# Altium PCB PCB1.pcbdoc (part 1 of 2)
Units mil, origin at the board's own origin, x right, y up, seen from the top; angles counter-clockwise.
Board outline 3120 x 2755.91 mil, 2 copper layers (Top Layer, Bottom Layer), stack 62.205 mil thick; 41 components, 124 nets, 614 pads, 395 vias.
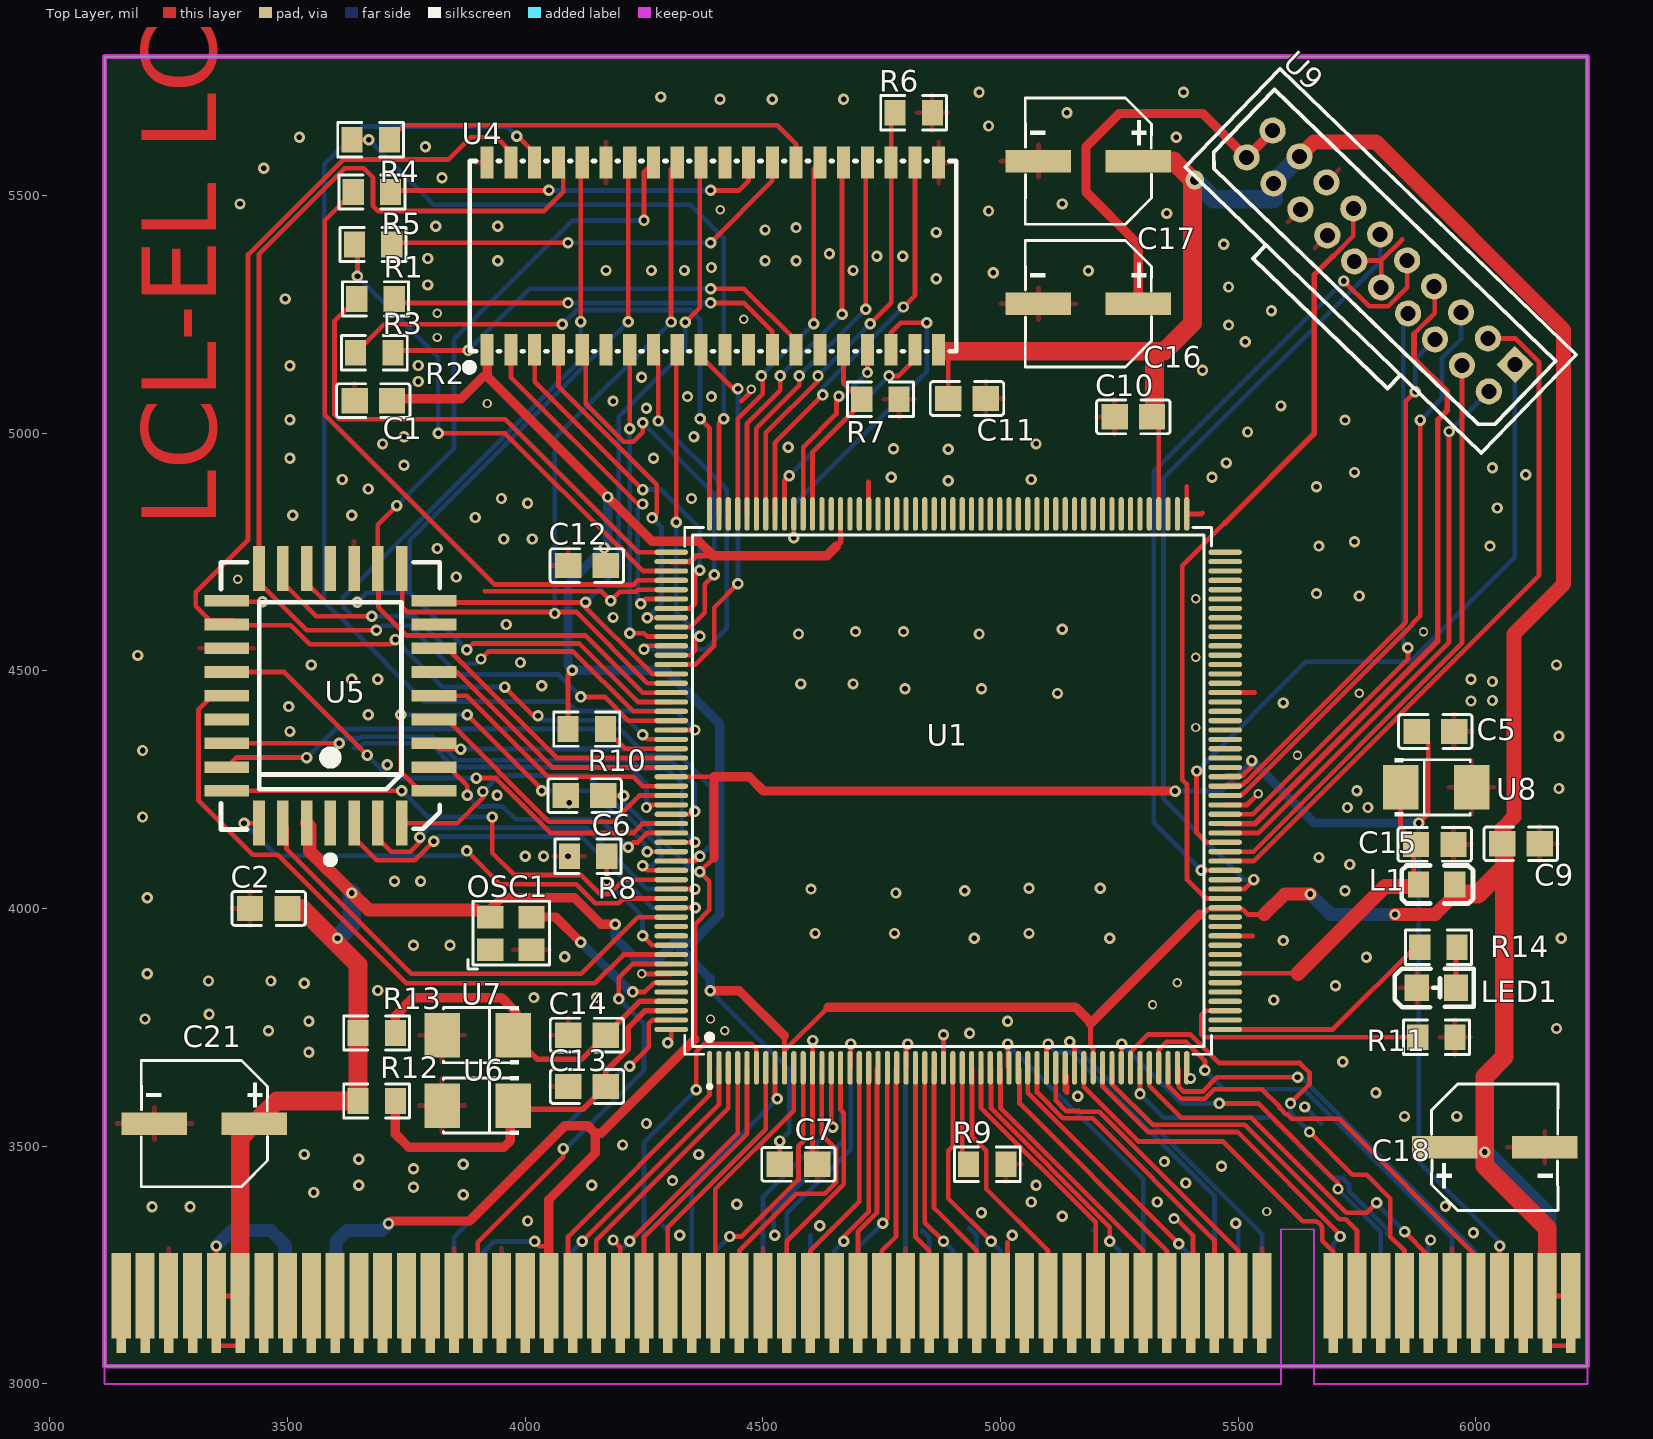
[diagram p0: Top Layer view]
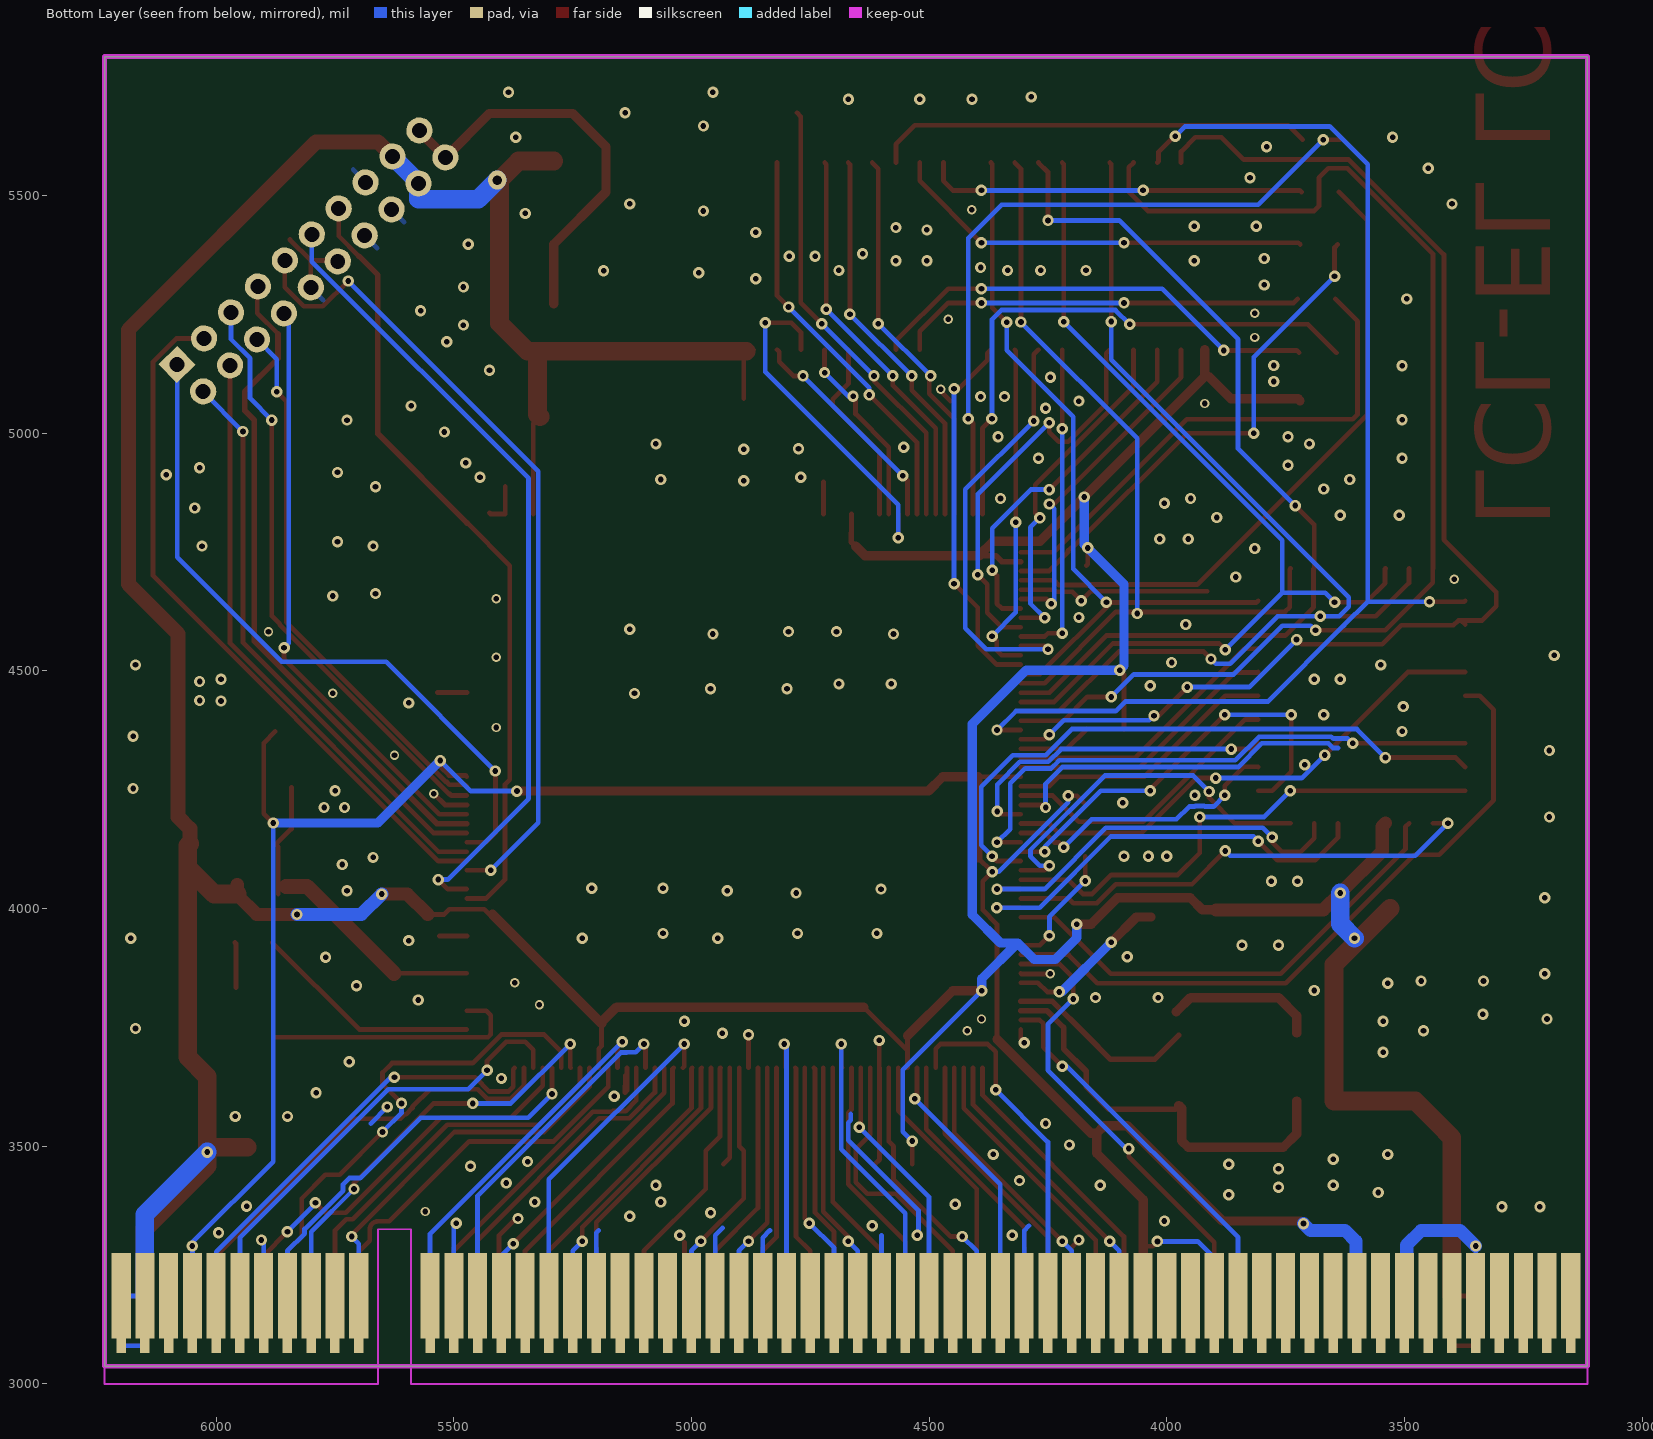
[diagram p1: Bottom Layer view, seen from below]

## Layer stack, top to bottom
Top Solder Mask Layer: solder mask 0.394, Dk 3.3
Top Layer: signal copper 1.378
Dielectric1: surface 59.449, FR4, Dk 4.5
Bottom Layer: signal copper 1.378
Bottom Solder Mask Layer: solder mask 0.394, Dk 3.3

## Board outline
3115,3036.77 3115,5792.68 6235,5792.68 6235,3036.77

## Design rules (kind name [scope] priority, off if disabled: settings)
BoardOutlineClearance copperThickness1oz [All] p0: genericclearance=10 ignorepadtopadclearanceinfootprint=FALSE except(0: Arc-SplitContinuation Track-SplitContinuation SMDPad-SplitContinuation THPad-SplitContinuation Via-SplitContinuation Fill-SplitContinuation Poly-SplitContinuation Region-SplitContinuation Text-SplitContinuation)
BoardOutlineClearance copperThickness2oz [All] p0: genericclearance=10 ignorepadtopadclearanceinfootprint=FALSE except(0: Arc-SplitContinuation Track-SplitContinuation SMDPad-SplitContinuation THPad-SplitContinuation Via-SplitContinuation Fill-SplitContinuation Poly-SplitContinuation Region-SplitContinuation Text-SplitContinuation)
BoardOutlineClearance otherClearance [All] p0: genericclearance=10 ignorepadtopadclearanceinfootprint=FALSE except(0: Arc-SplitContinuation Track-SplitContinuation SMDPad-SplitContinuation THPad-SplitContinuation Via-SplitContinuation Fill-SplitContinuation Poly-SplitContinuation Region-SplitContinuation Text-SplitContinuation)
Clearance copperThickness1oz [All] p1: gap=7 ignorepadtopadclearanceinfootprint=FALSE
Clearance copperThickness2oz [All] p1: gap=7 ignorepadtopadclearanceinfootprint=FALSE
Clearance otherClearance [All] p1: gap=7 ignorepadtopadclearanceinfootprint=FALSE
DiffPairsRouting differentialPair [All] p1: maxuncoupledlength=10 minlimit=6 maxlimit=Infinity mostfreqgap=6 toplayer_minwidth=5 toplayer_prefwidth=10 toplayer_maxwidth=100 bottomlayer_minwidth=5 bottomlayer_prefwidth=10 bottomlayer_maxwidth=100
PasteMaskExpansion pasteMaskExpansion [All] p1: expansion=0
PlaneConnect innerPlane [All] p1: planeconnectstyle=Relief reliefexpansion=20 reliefentries=4 reliefconductorwidth=10 reliefairgap=10
PolygonConnect copperRegion [All] p1: connectstyle=Relief reliefentries=4 reliefconductorwidth=10 polygonreliefangle="90 Angle" airgapwidth=10
RoutingVias viaSize [All] p1: viastyle="Through Hole" holewidth=12.0078 minholewidth=11.811 maxholewidth=248.0314 width=12.0078 minwidth=11.811 maxwidth=248.0314
SolderMaskExpansion solderMaskExpansion [All] p1: useseparateexpansions=TRUE expansion=2 expansionbottom=2
Width copperThickness1oz [All] p1: maxlimit=100 minlimit=5 preferedwidth=10
Width copperThickness2oz [All] p1: maxlimit=100 minlimit=8 preferedwidth=10

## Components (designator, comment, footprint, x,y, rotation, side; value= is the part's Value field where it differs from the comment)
C1 "" C0805 3680.43,5068.67 r0 top
C2 "" C0805 3460.43,4000.26 r0 top
C5 "" C0805 5915,4372.68 r180 top
C6 "" C0805 4125,4237.68 r0 top
C7 "" C0805 4574.89,3461.83 r180 top
C9 "" C0805 6094.89,4136.34 r180 top
C10 "" C0805 5279.55,5034.5 r0 top
C11 "" C0805 4929.55,5073.17 r180 top
C12 "" C0805 4129.88,4721.6 r0 top
C13 "" C0805 4130.18,3625.57 r0 top
C14 "" C0805 4130.18,3733.67 r0 top
C15 "" C0805 5913.72,4135.01 r180 top
C16 "" CAP-SMD_BD6.3-L6.6-W6.6-LS7.3-FD 5185,5272.68 r180 top
C17 "" CAP-SMD_BD6.3-L6.6-W6.6-LS7.3-FD 5185,5572.68 r180 top
C18 "" CAP-SMD_BD6.3-L6.6-W6.6-LS7.3-FD 6040,3497.68 r0 top
C21 "" CAP-SMD_BD6.3-L6.6-W6.6-LS7.3-FD 3325,3547.68 r180 top
L1 "" L0805 5917.8,4050.44 r180 top
LED1 "" LED0805-FD 5917.16,3833.52 r180 top
OSC1 "" OSC-SMD_4P-L3.2-W2.5-BL 3970,3947.68 r0 top
R1 "" R0805 3685,5282.68 r0 top
R2 "" R0805 3682.5,5169.31 r0 top
R3 "" R0805 3680,5397.21 r180 top
R4 "" R0805 3675,5617.68 r180 top
R5 "" R0805 3677.5,5507.68 r180 top
R6 "" R0805 4817.34,5674.31 r0 top
R7 "" R0805 4747.34,5071.42 r0 top
R8 "" R0805 4132.34,4110.11 r180 top
R9 "" R0805 4972.34,3462.21 r0 top
R10 "" R0805 4129.55,4377.63 r180 top
R11 "" R0805 5917.22,3729.23 r180 top
R12 "" R0805 3687.51,3595.11 r180 top
R13 "" R0805 3687.51,3738.2 r180 top
R14 "" R0805 5921.4,3918.52 r0 top
U1 "" PQFP-208_L28.0-W28.0-P0.50-LS30.6-BL 4890,4247.68 r0 top
U4 "" SOJ-40_L26.0-W10.2-P1.27-LS11.2-BL 4395,5372.68 r0 top
U5 "" PLCC-32_L14.0-W11.4-P1.27-LS15.0-T 3590,4447.68 r180 top
U6 "" CAP-SMD_L3.5-W2.8-R-RD 3899.88,3585.57 r0 top
U7 "" CAP-SMD_L3.5-W2.8-R-RD 3899.88,3733.67 r0 top
U8 "" CAP-SMD_L3.5-W2.8-R-RD 5916.59,4255.01 r180 top
U9 "" 20PIN-2.0MM_2_10 5800,5362.68 r316 top
? "" BUS_PCI-KiCAD 4675,3132.68 r0 top

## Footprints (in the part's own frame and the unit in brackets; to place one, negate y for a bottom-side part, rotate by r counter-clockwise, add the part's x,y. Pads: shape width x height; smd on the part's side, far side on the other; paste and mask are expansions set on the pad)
20PIN-2.0MM_2_10 [mm]
  rect 1.4x1.4 hole 0.8: 1(9,1)
  round 1.4 hole 0.8: 2(9,-1) 3(7,1) 4(7,-1) 5(5,1) 6(5,-1) 7(3,1) 8(3,-1) 9(1,1) 10(1,-1) 11(-1,1) 12(-1,-1) 13(-3,1) 14(-3,-1) 15(-5,1) 16(-5,-1) 17(-7,1) 18(-7,-1) 19(-9,1) 20(-9,-1)
  silkscreen extent -11,-4.65 11,3.65
BUS_PCI-KiCAD [mm]
  rect 0.51x0.76 smd far side: A1(-38.73,-1.33) A2(-37.46,-1.33) A3(-36.2,-1.33) A4(-34.92,-1.33) A5(-33.65,-1.33) A6(-32.38,-1.33) A7(-31.11,-1.33) A8(-29.84,-1.33) A9(-28.57,-1.33) A10(-27.3,-1.33) A11(-26.03,-1.33) A12(-24.77,-1.33) A13(-23.49,-1.33) A14(-22.22,-1.33) A15(-20.95,-1.33) A16(-19.68,-1.33) A17(-18.41,-1.33) A18(-17.14,-1.33) A19(-15.88,-1.33) A20(-14.6,-1.33) A21(-13.34,-1.33) A22(-12.06,-1.33) A23(-10.79,-1.33) A24(-9.52,-1.33) A25(-8.25,-1.33) A26(-6.98,-1.33) A27(-5.71,-1.33) A28(-4.44,-1.33) A29(-3.17,-1.33) A30(-1.9,-1.33) A31(-0.63,-1.33) A32(0.64,-1.33) A33(1.91,-1.33) A34(3.18,-1.33) A35(4.45,-1.33) A36(5.72,-1.33) A37(6.99,-1.33) A38(8.26,-1.33) A39(9.53,-1.33) A40(10.8,-1.33) A41(12.07,-1.33) A42(13.34,-1.33) A43(14.61,-1.33) A44(15.88,-1.33) A45(17.15,-1.33) A46(18.42,-1.33) A47(19.69,-1.33) A48(20.96,-1.33) A49(22.23,-1.33) A52(26.04,-1.33) A53(27.31,-1.33) A54(28.58,-1.33) A55(29.85,-1.33) A56(31.12,-1.33) A57(32.39,-1.33) A58(33.66,-1.33) A59(34.93,-1.33) A60(36.2,-1.33) A61(37.47,-1.33) A62(38.73,-1.33)
  rect 1.02x4.57 smd far side: A1(-38.73,1.33) A2(-37.46,1.33) A3(-36.2,1.33) A4(-34.92,1.33) A5(-33.65,1.33) A6(-32.38,1.33) A7(-31.11,1.33) A8(-29.84,1.33) A9(-28.57,1.33) A10(-27.3,1.33) A11(-26.03,1.33) A12(-24.77,1.33) A13(-23.49,1.33) A14(-22.22,1.33) A15(-20.95,1.33) A16(-19.68,1.33) A17(-18.41,1.33) A18(-17.14,1.33) A19(-15.88,1.33) A20(-14.6,1.33) A21(-13.34,1.33) A22(-12.06,1.33) A23(-10.79,1.33) A24(-9.52,1.33) A25(-8.25,1.33) A26(-6.98,1.33) A27(-5.71,1.33) A28(-4.44,1.33) A29(-3.17,1.33) A30(-1.9,1.33) A31(-0.63,1.33) A32(0.64,1.33) A33(1.91,1.33) A34(3.18,1.33) A35(4.45,1.33) A36(5.72,1.33) A37(6.99,1.33) A38(8.26,1.33) A39(9.53,1.33) A40(10.8,1.33) A41(12.07,1.33) A42(13.34,1.33) A43(14.61,1.33) A44(15.88,1.33) A45(17.15,1.33) A46(18.42,1.33) A47(19.69,1.33) A48(20.96,1.33) A49(22.23,1.33) A52(26.04,1.33) A53(27.31,1.33) A54(28.58,1.33) A55(29.85,1.33) A56(31.12,1.33) A57(32.39,1.33) A58(33.66,1.33) A59(34.93,1.33) A60(36.2,1.33) A61(37.47,1.33) A62(38.73,1.33)
  rect 0.51x0.76 smd: B1(-38.73,-1.33) B2(-37.46,-1.33) B3(-36.2,-1.33) B4(-34.92,-1.33) B5(-33.65,-1.33) B6(-32.38,-1.33) B7(-31.11,-1.33) B8(-29.84,-1.33) B9(-28.57,-1.33) B10(-27.3,-1.33) B11(-26.03,-1.33) B12(-24.77,-1.33) B13(-23.49,-1.33) B14(-22.22,-1.33) B15(-20.95,-1.33) B16(-19.68,-1.33) B17(-18.41,-1.33) B18(-17.14,-1.33) B19(-15.88,-1.33) B20(-14.6,-1.33) B21(-13.34,-1.33) B22(-12.06,-1.33) B23(-10.79,-1.33) B24(-9.52,-1.33) B25(-8.25,-1.33) B26(-6.98,-1.33) B27(-5.71,-1.33) B28(-4.44,-1.33) B29(-3.17,-1.33) B30(-1.9,-1.33) B31(-0.63,-1.33) B32(0.64,-1.33) B33(1.91,-1.33) B34(3.18,-1.33) B35(4.45,-1.33) B36(5.72,-1.33) B37(6.99,-1.33) B38(8.26,-1.33) B39(9.53,-1.33) B40(10.8,-1.33) B41(12.07,-1.33) B42(13.34,-1.33) B43(14.61,-1.33) B44(15.88,-1.33) B45(17.15,-1.33) B46(18.42,-1.33) B47(19.69,-1.33) B48(20.96,-1.33) B49(22.23,-1.33) B52(26.04,-1.33) B53(27.31,-1.33) B54(28.58,-1.33) B55(29.85,-1.33) B56(31.12,-1.33) B57(32.39,-1.33) B58(33.66,-1.33) B59(34.93,-1.33) B60(36.2,-1.33) B61(37.47,-1.33) B62(38.73,-1.33)
  rect 1.02x4.57 smd: B1(-38.73,1.33) B2(-37.46,1.33) B3(-36.2,1.33) B4(-34.92,1.33) B5(-33.65,1.33) B6(-32.38,1.33) B7(-31.11,1.33) B8(-29.84,1.33) B9(-28.57,1.33) B10(-27.3,1.33) B11(-26.03,1.33) B12(-24.77,1.33) B13(-23.49,1.33) B14(-22.22,1.33) B15(-20.95,1.33) B16(-19.68,1.33) B17(-18.41,1.33) B18(-17.14,1.33) B19(-15.88,1.33) B20(-14.6,1.33) B21(-13.34,1.33) B22(-12.06,1.33) B23(-10.79,1.33) B24(-9.52,1.33) B25(-8.25,1.33) B26(-6.98,1.33) B27(-5.71,1.33) B28(-4.44,1.33) B29(-3.17,1.33) B30(-1.9,1.33) B31(-0.63,1.33) B32(0.64,1.33) B33(1.91,1.33) B34(3.18,1.33) B35(4.45,1.33) B36(5.72,1.33) B37(6.99,1.33) B38(8.26,1.33) B39(9.53,1.33) B40(10.8,1.33) B41(12.07,1.33) B42(13.34,1.33) B43(14.61,1.33) B44(15.88,1.33) B45(17.15,1.33) B46(18.42,1.33) B47(19.69,1.33) B48(20.96,1.33) B49(22.23,1.33) B52(26.04,1.33) B53(27.31,1.33) B54(28.58,1.33) B55(29.85,1.33) B56(31.12,1.33) B57(32.39,1.33) B58(33.66,1.33) B59(34.93,1.33) B60(36.2,1.33) B61(37.47,1.33) B62(38.73,1.33)
  Board Outline Layer lines w0.1: -39.62,-3.37 -39.62,4.89 -39.62,-3.37 ; -39.62,-3.37 23.24,-3.37 ; -39.62,-3.37 23.24,-3.37 ; 23.24,-3.37 23.24,4.89 ; 23.24,-3.37 23.24,4.89 ; 23.24,4.89 25.02,4.89 ; 23.24,4.89 25.02,4.89 ; 25.02,-3.37 25.02,4.89 ; 25.02,-3.37 25.02,4.89 ; 25.02,-3.37 39.62,-3.37 ; 25.02,-3.37 39.62,-3.37 ; 39.62,-3.37 39.62,4.89 39.62,-3.37
C0805 [mm]
  rect 1.41x1.35 smd: 1(-1,0) 2(1,0)
  silkscreen extent -1.96,-0.9 1.96,0.9
CAP-SMD_BD6.3-L6.6-W6.6-LS7.3-FD [mm]
  rect 3.5x1.2 smd: 1(-2.67,0) 2(2.67,0)
  silkscreen extent -3.38,-3.38 3.38,3.38
CAP-SMD_L3.5-W2.8-R-RD [mm]
  rect 1.9x2.376 smd: 1(1.899,0) 2(-1.899,0)
  silkscreen extent -1.83,-1.55 2.21,1.55
L0805 [mil]
  rect 44.59x54.21 smd: 1(-38.04,0) 2(38.04,0)
  silkscreen extent -77,-40 73,40
LED0805-FD [mil]
  rect 51.2x55.1 smd: 1(-41.35,0) 2(41.35,0)
  silkscreen extent -78,-40 88,41
OSC-SMD_4P-L3.2-W2.5-BL [mm]
  rect 1.4x1.2 smd: 1(-1.1,-0.875) 2(1.1,-0.875) 3(1.1,0.875) 4(-1.1,0.875)
  silkscreen extent -2.29,-1.9 2.07,1.72
PLCC-32_L14.0-W11.4-P1.27-LS15.0-T [mm]
  rect 0.62x2.4 smd: 1(0,6.805) 2(-1.27,6.805) 3(-2.54,6.805) 4(-3.81,6.805) 14(-3.81,-6.805) 15(-2.54,-6.805) 16(-1.27,-6.805) 17(0,-6.805) 18(1.27,-6.805) 19(2.54,-6.805) 20(3.81,-6.805) 30(3.81,6.805) 31(2.54,6.805) 32(1.27,6.805)
  rect 2.4x0.62 smd: 5(-5.535,5.08) 6(-5.535,3.81) 7(-5.535,2.54) 8(-5.535,1.27) 9(-5.535,0) 10(-5.535,-1.27) 11(-5.535,-2.54) 12(-5.535,-3.81) 13(-5.535,-5.08) 21(5.535,-5.08) 22(5.535,-3.81) 23(5.535,-2.54) 24(5.535,-1.27) 25(5.535,0) 26(5.535,1.27) 27(5.535,2.54) 28(5.535,3.81) 29(5.535,5.08)
  silkscreen extent -5.84,-7.14 5.84,8.96
PQFP-208_L28.0-W28.0-P0.50-LS30.6-BL [mm]
  oval 0.28x1.8 smd: 1(-12.75,-14.8) 2(-12.25,-14.8) 3(-11.75,-14.8) 4(-11.25,-14.8) 5(-10.75,-14.8) 6(-10.25,-14.8) 7(-9.75,-14.8) 8(-9.25,-14.8) 9(-8.75,-14.8) 10(-8.25,-14.8) 11(-7.75,-14.8) 12(-7.25,-14.8) 13(-6.75,-14.8) 14(-6.25,-14.8) 15(-5.75,-14.8) 16(-5.25,-14.8) 17(-4.75,-14.8) 18(-4.25,-14.8) 19(-3.75,-14.8) 20(-3.25,-14.8) 21(-2.75,-14.8) 22(-2.25,-14.8) 23(-1.75,-14.8) 24(-1.25,-14.8) 25(-0.75,-14.8) 26(-0.25,-14.8) 27(0.25,-14.8) 28(0.75,-14.8) 29(1.25,-14.8) 30(1.75,-14.8) 31(2.25,-14.8) 32(2.75,-14.8) 33(3.25,-14.8) 34(3.75,-14.8) 35(4.25,-14.8) 36(4.75,-14.8) 37(5.25,-14.8) 38(5.75,-14.8) 39(6.25,-14.8) 40(6.75,-14.8) 41(7.25,-14.8) 42(7.75,-14.8) 43(8.25,-14.8) 44(8.75,-14.8) 45(9.25,-14.8) 46(9.75,-14.8) 47(10.25,-14.8) 48(10.75,-14.8) 49(11.25,-14.8) 50(11.75,-14.8) 51(12.25,-14.8) 52(12.75,-14.8) 105(12.75,14.8) 106(12.25,14.8) 107(11.75,14.8) 108(11.25,14.8) 109(10.75,14.8) 110(10.25,14.8) 111(9.75,14.8) 112(9.25,14.8) 113(8.75,14.8) 114(8.25,14.8) 115(7.75,14.8) 116(7.25,14.8) 117(6.75,14.8) 118(6.25,14.8) 119(5.75,14.8) 120(5.25,14.8) 121(4.75,14.8) 122(4.25,14.8) 123(3.75,14.8) 124(3.25,14.8) 125(2.75,14.8) 126(2.25,14.8) 127(1.75,14.8) 128(1.25,14.8) 129(0.75,14.8) 130(0.25,14.8) 131(-0.25,14.8) 132(-0.75,14.8) 133(-1.25,14.8) 134(-1.75,14.8) 135(-2.25,14.8) 136(-2.75,14.8) 137(-3.25,14.8) 138(-3.75,14.8) 139(-4.25,14.8) 140(-4.75,14.8) 141(-5.25,14.8) 142(-5.75,14.8) 143(-6.25,14.8) 144(-6.75,14.8) 145(-7.25,14.8) 146(-7.75,14.8) 147(-8.25,14.8) 148(-8.75,14.8) 149(-9.25,14.8) 150(-9.75,14.8) 151(-10.25,14.8) 152(-10.75,14.8) 153(-11.25,14.8) 154(-11.75,14.8) 155(-12.25,14.8) 156(-12.75,14.8)
  oval 1.8x0.28 smd: 53(14.8,-12.75) 54(14.8,-12.25) 55(14.8,-11.75) 56(14.8,-11.25) 57(14.8,-10.75) 58(14.8,-10.25) 59(14.8,-9.75) 60(14.8,-9.25) 61(14.8,-8.75) 62(14.8,-8.25) 63(14.8,-7.75) 64(14.8,-7.25) 65(14.8,-6.75) 66(14.8,-6.25) 67(14.8,-5.75) 68(14.8,-5.25) 69(14.8,-4.75) 70(14.8,-4.25) 71(14.8,-3.75) 72(14.8,-3.25) 73(14.8,-2.75) 74(14.8,-2.25) 75(14.8,-1.75) 76(14.8,-1.25) 77(14.8,-0.75) 78(14.8,-0.25) 79(14.8,0.25) 80(14.8,0.75) 81(14.8,1.25) 82(14.8,1.75) 83(14.8,2.25) 84(14.8,2.75) 85(14.8,3.25) 86(14.8,3.75) 87(14.8,4.25) 88(14.8,4.75) 89(14.8,5.25) 90(14.8,5.75) 91(14.8,6.25) 92(14.8,6.75) 93(14.8,7.25) 94(14.8,7.75) 95(14.8,8.25) 96(14.8,8.75) 97(14.8,9.25) 98(14.8,9.75) 99(14.8,10.25) 100(14.8,10.75) 101(14.8,11.25) 102(14.8,11.75) 103(14.8,12.25) 104(14.8,12.75) 157(-14.8,12.75) 158(-14.8,12.25) 159(-14.8,11.75) 160(-14.8,11.25) 161(-14.8,10.75) 162(-14.8,10.25) 163(-14.8,9.75) 164(-14.8,9.25) 165(-14.8,8.75) 166(-14.8,8.25) 167(-14.8,7.75) 168(-14.8,7.25) 169(-14.8,6.75) 170(-14.8,6.25) 171(-14.8,5.75) 172(-14.8,5.25) 173(-14.8,4.75) 174(-14.8,4.25) 175(-14.8,3.75) 176(-14.8,3.25) 177(-14.8,2.75) 178(-14.8,2.25) 179(-14.8,1.75) 180(-14.8,1.25) 181(-14.8,0.75) 182(-14.8,0.25) 183(-14.8,-0.25) 184(-14.8,-0.75) 185(-14.8,-1.25) 186(-14.8,-1.75) 187(-14.8,-2.25) 188(-14.8,-2.75) 189(-14.8,-3.25) 190(-14.8,-3.75) 191(-14.8,-4.25) 192(-14.8,-4.75) 193(-14.8,-5.25) 194(-14.8,-5.75) 195(-14.8,-6.25) 196(-14.8,-6.75) 197(-14.8,-7.25) 198(-14.8,-7.75) 199(-14.8,-8.25) 200(-14.8,-8.75) 201(-14.8,-9.25) 202(-14.8,-9.75) 203(-14.8,-10.25) 204(-14.8,-10.75) 205(-14.8,-11.25) 206(-14.8,-11.75) 207(-14.8,-12.25) 208(-14.8,-12.75)
  silkscreen extent -14.08,-15.9 14.08,14.08
R0805 [mm]
  rect 1.133x1.377 smd: 1(-1,0) 2(1,0)
  silkscreen extent -1.76,-0.92 1.76,0.92
SOJ-40_L26.0-W10.2-P1.27-LS11.2-BL [mm]
  rect 0.7x1.7 smd: 1(-12.065,-5) 2(-10.795,-5) 3(-9.525,-5) 4(-8.255,-5) 5(-6.985,-5) 6(-5.715,-5) 7(-4.445,-5) 8(-3.175,-5) 9(-1.905,-5) 10(-0.635,-5) 11(0.635,-5) 12(1.905,-5) 13(3.175,-5) 14(4.445,-5) 15(5.715,-5) 16(6.985,-5) 17(8.255,-5) 18(9.525,-5) 19(10.795,-5) 20(12.065,-5) 21(12.065,5) 22(10.795,5) 23(9.525,5) 24(8.255,5) 25(6.985,5) 26(5.715,5) 27(4.445,5) 28(3.175,5) 29(1.905,5) 30(0.635,5) 31(-0.635,5) 32(-1.905,5) 33(-3.175,5) 34(-4.445,5) 35(-5.715,5) 36(-6.985,5) 37(-8.255,5) 38(-9.525,5) 39(-10.795,5) 40(-12.065,5)
  silkscreen extent -13.22,-6.14 13,5.08

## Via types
v1: diameter 23.62, hole 11.81, Top Layer to Bottom Layer, 223 vias
v2: diameter 24.02, hole 12.01, Top Layer to Bottom Layer, 148 vias
v3: diameter 19.68, hole 11.81, Top Layer to Bottom Layer, 20 vias
v4: diameter 23.62, hole 12.01, Top Layer to Bottom Layer, 3 vias
v5: diameter 39.37, hole 19.68, Top Layer to Bottom Layer, 1 vias

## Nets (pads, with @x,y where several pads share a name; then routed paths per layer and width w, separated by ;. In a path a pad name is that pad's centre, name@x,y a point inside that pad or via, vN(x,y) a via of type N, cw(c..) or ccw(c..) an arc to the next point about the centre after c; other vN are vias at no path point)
12V: ?.A2 C16.1 U9.19 U9.20 | length 859.9
  Top Layer w19.68: C16.1@5290.12,5272.68 5290.12,5397.56 5180,5507.68 5180,5602.68 5250,5672.68 5425.59,5672.68 U9.20@5517.77,5580.5 5572.46,5635.19 U9.19@5572.46,5637.14
14.318: OSC1.3 U1.203 | length 347.4
  Top Layer w9.92: v2(4226.62,3824.54) 4251.86,3824.54 4271.46,3844.14 U1.203@4307.32,3844.14
  Top Layer w19.68: OSC1.3@4033.31,3982.13 4064.03,3982.13 v2(4117.02,3929.14)
  Bottom Layer w19.68: v2(4117.02,3929.14) 4221.62,3824.54 v2(4226.62,3824.54)
$1N39: R10.1 U1.178 | length 155.5
  Top Layer w9.92: R10.1@4168.91,4377.63 4210.29,4336.26 U1.178@4307.32,4336.26
$1N59: R1.2 U4.13 | length 862.4
  Top Layer w10: R1.2@3724.37,5282.68 3732.76,5274.29 v2(4090,5274.29) ; v2(4390,5274.29) 4460,5274.29 4520,5214.29 U4.13@4520,5175.83
  Bottom Layer w10: v2(4090,5274.29) v2(4390,5274.29)
$1N61: R2.2 U4.14 | length 968.1
  Top Layer w10: R2.2@3721.87,5169.31 3726.85,5174.29 v2(3880,5174.29) ; v2(4390,5304.29) 4460,5304.29 4570,5194.29 U4.14@4570,5175.83
  Bottom Layer w10: v2(3880,5174.29) 4010,5304.29 v2(4390,5304.29)
$1N62: R4.1 U4.27 | length 923.2
  Top Layer w10: R4.1@3714.37,5617.68 3744.68,5647.99 4530,5647.99 4570,5607.99 U4.27@4570,5569.53
$1N63: R3.1 U4.28 | length 894.5
  Top Layer w10: R3.1@3719.37,5397.21 3723.22,5401.06 v2(4090,5401.06) ; v2(4390,5401.06) 4520,5531.06 U4.28@4520,5569.53
  Bottom Layer w10: v2(4090,5401.06) v2(4390,5401.06)
$1N64: R5.1 U4.29 | length 801.3
  Top Layer w10: R5.1@3716.87,5507.68 3720.25,5511.06 v2(4050,5511.06) ; v2(4390,5511.06) 4450,5511.06 4470,5531.06 U4.29@4470,5569.53
  Bottom Layer w10: v2(4050,5511.06) v2(4390,5511.06)
$1N313: R11.2 U1.55 | length 552.4
  Top Layer w9.92: U1.55@5472.68,3785.08 5432.37,3785.08 5422.37,3775.08 5422.37,3735.08 5428.21,3729.23 R11.2@5877.85,3729.23
$1N327: C15.2 L1.2 U1.59 U8.1 | length 696.4
  Top Layer w9.92: U1.59@5472.68,3863.82 5626.14,3863.82
  Top Layer w10: U8.1@5841.84,4255.01 5841.83,4167.53 C15.2@5874.35,4135.01 5869.61,4130.27 L1.2@5869.61,4030.44
  Top Layer w31.5: 5626.14,3863.82 5809.16,4046.84 5853.22,4046.84
$1N354: C13.2 R12.1 U1.206 U6.1 | length 871.9
  Top Layer w11.81: U6.1@3974.63,3585.57 3982.52,3577.68 4121.65,3577.68 C13.2@4169.55,3625.57 4169.55,3657.61 4217.02,3705.08 4217.02,3749.69 4252.4,3785.08 U1.206@4307.32,3785.08
  Top Layer w19.68: R12.1@3726.88,3595.11 3726.88,3525.8 3755,3497.68 3955,3497.68 3968.92,3511.6 3968.92,3579.86 U6.1@3974.63,3585.57
$1N355: C14.2 R13.1 U1.205 U7.1 | length 722.1
  Top Layer w11.81: U7.1@3974.63,3733.67 4025.62,3682.68 4118.56,3682.68 C14.2@4169.55,3733.67 4240.65,3804.77 U1.205@4307.32,3804.77
  Top Layer w19.68: R13.1@3726.88,3738.2 3726.88,3774.55 3765,3812.68 3950,3812.68 3980,3782.68
$1N392: R14.1 U1.53 | length 485.1
  Top Layer w9.92: U1.53@5472.68,3745.71 5699.22,3745.71 R14.1@5882.03,3928.52
$1N395: LED1.1 R14.2 | length 95.9
  Top Layer w10: LED1.1@5958.51,3833.52 5958.51,3926.26 R14.2@5960.77,3928.52
+5V: ?.A5 ?.A8 ?.A61 ?.A62 ?.B5 ?.B6 ?.B61 ?.B62 C1.2 C2.2 C7.2 C9.2 C10.2 C11.2 C12.2 C17.1 C18.1 C21.1 L1.1 OSC1.4 R10.2 R12.2 R13.2 U1.9 U1.42 U1.66 U1.108 U1.142 U1.158 U4.1 U4.20 U5.32 U9.17 U9.18 | length 14011.4
  Top Layer w9.92: v2(4166.43,4758.78) 4166.43,4724.41 C12.2@4169.25,4721.6 ; C7.2@4535.52,3461.83 v2(4535.52,3510.86) ; U1.9@4545.51,3665 4545.51,3700.86 ; 4545.51,3732.17 4545.51,3700.86 ; 4637.32,3792.68 4545.51,3700.86 ; 4663.62,4790.04 U1.142@4663.62,4830.35 ; 5189.26,3761.11 5189.26,3758.2 5189.26,3710.86 5195.12,3705 U1.42@5195.12,3665 ; C10.2@5318.91,5034.5 5332.91,5020.51 U1.108@5332.91,4830.35 ; 5418.74,3987.68 5425.23,3987.68 5435.94,3998.38 5509.41,3998.38 5520.12,3987.68 5555,3987.68
  Top Layer w10: v2(3350.2,3290) ?.B5@3350.2,3185.04 ; ?.B6@3400.2,3080.31 ?.B5@3350.2,3080.31 ?.B5@3350.2,3185.04 ; ?.B6@3400.2,3185.04 ?.B5@3350.2,3185.04 ; R10.2@4090.18,4377.63 4090.18,4492.52 v2(4099.25,4501.59) ; v5@5404.02,5532.68 v5(5409.02,5532.68) ; ?.B62@6199.8,3080.31 ?.B61@6150.19,3080.31 ?.B61@6150.19,3185.04 ?.B62@6199.8,3185.04
  Top Layer w10.24: U4.20@4870,5175.83 4890.18,5155.65 C11.2@4890.18,5073.17
  Top Layer w11.81: U1.158@4307.32,4729.96 4347.28,4729.96 4360,4742.68 4395,4742.68 ; 4655,4762.68 4663.62,4771.3 4663.62,4790.04
  Top Layer w19.68: C1.2@3719.8,5068.67 3723.81,5072.68 3865,5072.68 3911.91,5119.59 3920,5119.59 ; 3896.69,3997.13 3925.06,3997.13 3950.61,4022.68 4103.7,4022.68 4159.25,3967.13 v2(4189.25,3967.13) ; U4.1@3920,5175.83 3920,5119.59 ; v2(4389.25,3827.13) 4450.55,3827.13 4545.51,3732.17 ; 4637.32,3792.68 5157.69,3792.68 5189.26,3761.11 ; 4655,4762.68 4635,4742.68 4395,4742.68 4365,4772.68 4266.91,4772.68 v2(4173.62,4865.97) 3920,5119.59 ; 5189.26,3758.2 5418.74,3987.68
  Top Layer w27.56: U5.32@3540,4179.76 3546.69,4173.07 3546.69,4120.99 v4(3635,4032.68) 3670.55,3997.13 3896.69,3997.13 ; 5555,3987.68 5597.76,4030.44 v2(5651.81,4030.44) ; v4(5830,3987.68) 5915,3987.68 5955.84,4028.52 5955.84,4030.44 L1.1@5955.84,4050.44
  Top Layer w31.5: U9.17@5629.11,5582.44 5659.34,5612.68 5790,5612.68 6185,5217.68 6185,4682.68 6080,4577.68 6080,4192.68 6055.52,4168.2 C9.2@6055.52,4136.34
  Top Layer w39.37: ?.B6@3400.2,3185.04 3400.2,3517.76 C21.1@3430.12,3547.68 3477.55,3595.11 R12.2@3648.14,3595.11 R13.2@3648.14,3738.2 3648.14,3881.93 3529.8,4000.26 ; 4885,5172.68 5324.02,5172.68 ; C17.1@5290.12,5572.68 5364.02,5572.68 5404.02,5532.68 5404.02,5231.7 5345,5172.68 5324.02,5172.68 ; C10.2@5318.91,5034.5 5324.02,5039.61 5324.02,5172.68 ; C18.1@5934.88,3497.68 6008.77,3497.68 ; L1.1@5955.84,4030.44 6004.44,4030.44 6060,4086 ; C9.2@6055.52,4136.34 6060,4131.86 6060,4086 ; ?.B61@6150.19,3185.04 6150.2,3327.48 6018.77,3458.9 v2(6018.77,3487.68) 6018.77,3646.45 6060,3687.68 6060,4086
  Bottom Layer w9.92: v2(4389.25,3827.13) 4555.52,3660.86 4555.52,3530.86 v2(4535.52,3510.86)
  Bottom Layer w10: ?.A5@3350.2,3080.31 ?.A5@3350.2,3185.04 v2(3350.2,3290) ; ?.A8@3500.2,3080.31 ?.A8@3500.2,3185.04 ; ?.A62@6199.8,3080.31 ?.A61@6150.19,3080.31 ?.A61@6150.19,3185.04 ?.A62@6199.8,3185.04
  Bottom Layer w19.68: v2(4173.62,4865.97) 4173.62,4765.97 v2(4166.43,4758.78) 4090,4682.35 4090,4510.84 v2(4099.25,4501.59) 4296.08,4501.59 4409.25,4388.43 4409.25,4264.47 4409.33,4264.38 4409.33,3987.01 4350,3927.68 4313.98,3927.68 ; v2(4189.25,3967.13) 4189.25,3938.43 4234.9,3892.78 4279.08,3892.78 4313.98,3927.68 ; v2(4389.25,3827.13) 4389.25,3852.41 4313.98,3927.68
  Bottom Layer w27.56: v2(3350.2,3290) 3382.88,3322.68 3465,3322.68 3495.24,3292.44 3495.24,3190 ?.A8@3500.2,3185.04 ; v2(5651.81,4030.44) 5694.57,3987.68 v4(5830,3987.68)
  Bottom Layer w39.37: v4(3605,3937.68) 3635,3967.68 v4(3635,4032.68) ; v5(5409.02,5532.68) 5449.02,5492.68 5574.41,5492.68 5574.41,5527.74 U9.17@5629.11,5582.44 ; v2(6018.77,3487.68) 6150.2,3356.26 ?.A61@6150.19,3185.04
A0: R7.1 U1.145 U4.16 | length 399.9
  Top Layer w9.92: U1.145@4604.57,4830.35 4604.57,4960.66 4702.97,5059.06 R7.1@4702.97,5071.42
  Top Layer w10: U4.16@4670,5175.83 4670,5104.38 R7.1@4702.97,5071.42
A1: U1.146 U4.17 | length 415.2
  Top Layer w9.92: U1.146@4584.88,4830.35 4584.88,4970.66 4654.88,5040.66 v1@4654.88,5082.68
  Top Layer w10.24: v1(4720,5127.68) U4.17@4720,5175.83
  Bottom Layer w10.24: v1@4655,5077.68 4670,5077.68 v1(4720,5127.68)
  other v1: 4660,5077.68
A2: U1.147 U4.18 | length 739
  Top Layer w9.92: v2(4565.2,4780.04) U1.147@4565.2,4830.35
  Top Layer w10.24: U4.18@4770,5175.83 4770,5212.68 4790,5232.68 v1(4845,5232.68)
  Bottom Layer w9.92: v2(4565.2,4780.04) 4565.2,4849.26 4845,5129.06
  Bottom Layer w10.24: 4845,5129.06 v1(4845,5232.68)
A3: U1.148 U4.19 | length 470.9
  Top Layer w9.92: U1.148@4545.51,4830.35 4545.51,4900.66 v2(4555.51,4910.66) ; v2(4765.51,5120.66) 4785.51,5120.66 4815.51,5150.66 4815.51,5171.33 U4.19@4820,5175.83
  Bottom Layer w9.92: v2(4555.51,4910.66) v2(4765.51,5120.66)
A4: U1.149 U4.22 | length 861
  Top Layer w9.92: U1.149@4525.83,4830.35 4525.83,4980.66 v2(4625.83,5080.66) ; v2(4795.83,5265.66) 4820,5289.83 U4.22@4820,5569.53
  Bottom Layer w9.92: v2(4625.83,5080.66) 4625.83,5095.66 v2(4795.83,5265.66)
A5: R6.1 U1.150 U4.23 | length 956.6
  Top Layer w9.92: U1.150@4506.14,4830.35 4506.14,5000.66 4616.14,5110.66 v2(4616.14,5120.66) ; v2(4726.14,5230.66) 4770,5274.52 U4.23@4770,5569.53
  Top Layer w10: U4.23@4770,5569.53 4770,5666.35 R6.1@4777.97,5674.31
  Bottom Layer w9.92: v2(4616.14,5120.66) v2(4726.14,5230.66)
A6: U1.151 U4.24 | length 835.9
  Top Layer w9.92: U1.151@4486.46,4830.35 4486.46,5010.66 4576.46,5100.66 v2(4576.46,5120.66) ; v2(4716.46,5260.66) 4716.46,5565.99 U4.24@4720,5569.53
  Bottom Layer w9.92: v2(4576.46,5120.66) v2(4716.46,5260.66)
A7: U1.152 U4.25 | length 823.4
  Top Layer w9.92: U1.152@4466.77,4830.35 4466.77,5020.66 4536.77,5090.66 v2(4536.77,5120.66) ; v2(4666.77,5250.66) 4666.77,5566.29 U4.25@4670,5569.53
  Bottom Layer w9.92: v2(4536.77,5120.66) v2(4666.77,5250.66)
A8: U1.153 U4.26 | length 813.2
  Top Layer w9.92: U1.153@4447.09,4830.35 4447.09,5030.66 4500,5083.57 4500,5117.76 v2(4497.09,5120.66) ; v2(4607.09,5230.66) 4607.09,5556.62 U4.26@4620,5569.53
  Bottom Layer w9.92: v2(4497.09,5120.66) v2(4607.09,5230.66)
AA2: U1.179 U5.11 | length 595.1
  Top Layer w9.92: U5.11@3807.92,4547.68 3809.02,4546.58 3837.02,4546.58 4067.02,4316.58 U1.179@4307.32,4316.58
AA3: U1.180 U5.10 | length 582.6
  Top Layer w9.92: U5.10@3807.92,4497.68 3808.71,4496.89 3857.02,4496.89 4057.02,4296.89 U1.180@4307.32,4296.89
AA4: U1.182 U5.9 | length 577.9
  Top Layer w9.92: U5.9@3808.08,4447.52 3877.02,4447.52 4047.02,4277.52 4227.02,4277.52 4247.01,4257.52 U1.182@4307.32,4257.52
AA5: U1.183 U5.8 | length 611.2
  Top Layer w9.92: U5.8@3808.07,4397.84 3834.84,4397.84 4050,4182.68 4185,4182.68 4240.16,4237.84 U1.183@4307.32,4237.84
AA6: U1.185 U5.7 | length 693.1
  Top Layer w9.92: U5.7@3807.92,4347.68 3820.07,4335.52 v2(3864.69,4335.52) ; U1.185@4307.32,4198.47 4350.81,4198.47 v2(4356.72,4204.38)
  Bottom Layer w9.92: v2(3864.69,4335.52) 4222.44,4335.52 4249.22,4308.74 4308.94,4308.74 4356.72,4260.96 v2(4356.72,4204.38)
AA7: U1.186 U5.24 | length 1083.9
  Top Layer w9.92: U5.24@3372.09,4497.68 3493.11,4497.68 v2(3667.9,4322.89) ; v2(3897.02,4274.57) 3938.11,4274.57 4053.9,4158.78 4227.02,4158.78 4247.01,4178.78 U1.186@4307.32,4178.78
  Bottom Layer w9.92: v2(3667.9,4322.89) 3716.22,4274.57 v2(3897.02,4274.57)
  other v1: 3710,4302.68
AA8: U1.187 U5.6 | length 594.7
  Top Layer w9.92: U5.6@3807.92,4297.68 3808.43,4298.2 3837.92,4298.2 3877.92,4258.2 v2(3877.92,4238.2) ; v2(4217.02,4129.1) 4227.02,4139.1 4237.02,4139.1 4257.01,4159.1 U1.187@4307.32,4159.1
  Bottom Layer w9.92: v2(3877.92,4238.2) 3901.51,4214.6 3920.21,4214.6 3921.28,4215.67 3940.29,4215.67 3941.35,4214.6 3952.79,4214.6 3979.71,4187.68 4158.44,4187.68 v2(4217.02,4129.1)
AA9: U1.188 U5.27 | length 1189.4
  Top Layer w9.92: U5.27@3372.09,4347.68 v2(3609.05,4347.68) ; U1.188@4307.32,4139.41 v2(4357.32,4139.41)
  Bottom Layer w9.92: v2(3609.05,4347.68) 3619.05,4357.68 3650.07,4357.68 3654.16,4361.77 3805.84,4361.77 3855.84,4311.77 4225.84,4311.77 4228.2,4309.41 4228.84,4309.41 4243.45,4294.8 4297.87,4294.8 4329.45,4263.23 4329.45,4167.28 v2(4357.32,4139.41)
AA10: U1.189 U5.5 | length 902.8
  Top Layer w9.92: v2(3737.92,4407.68) 3737.92,4287.68 3777.92,4247.68 U5.5@3807.92,4247.68 ; v2(3877.92,4407.68) 4034.97,4250.63 v2(4034.97,4247.68) ; v2(4257.01,4119.73) U1.189@4307.32,4119.73
  Bottom Layer w9.92: v2(3737.92,4407.68) v2(3877.92,4407.68) ; v2(4034.97,4247.68) 4139.06,4247.68 4257.01,4129.73 v2(4257.01,4119.73)
AA11: U1.190 U5.28 | length 1322.2
  Top Layer w9.92: U5.28@3372.09,4297.68 3392.09,4317.68 v2(3539.99,4317.68) ; U1.190@4307.32,4100.04 4357.64,4100.04 v2(4367.64,4110.04)
  Bottom Layer w9.92: v2(3539.99,4317.68) 3599.99,4377.68 4199.99,4377.68 4254.99,4322.68 4324.42,4322.68 4390.51,4256.59 4390.51,4132.91 v2(4367.64,4110.04)
AA12: U1.191 U5.4 | length 786.5
  Top Layer w9.92: U5.4@3740,4179.76 3857.61,4179.76 3911.12,4233.27 v2(3911.12,4246.25) ; v2(4247.01,4090.36) 4257.01,4080.36 U1.191@4307.32,4080.36
  Bottom Layer w9.92: v2(3911.12,4246.25) 3944.64,4279.76 4130.45,4279.76 4287.01,4123.2 4287.01,4110.36 4267.01,4090.36 v2(4247.01,4090.36)
AA13: U1.192 U5.29 | length 1082
  Top Layer w9.92: U5.29@3372.09,4247.68 v2(3740,4247.68) ; v2(3930.78,4192.71) 3930.78,4116.89 3977.01,4070.67 4117.02,4070.67 4157.02,4030.67 4177.02,4030.67 4207.02,4060.67 U1.192@4307.32,4060.67
  Bottom Layer w9.92: v2(3740,4247.68) 3794.97,4192.71 v2(3930.78,4192.71)
AA14: U1.193 U5.3 | length 840.5
  Top Layer w9.92: U5.3@3690,4179.76 3690,4148.32 3718.55,4119.76 3758.55,4119.76 3778.55,4139.76 v2(3778.55,4149.76) ; U1.193@4307.32,4040.99 v2(4357.32,4040.99)
  Bottom Layer w9.92: v2(3778.55,4149.76) 3798.55,4169.76 4128.55,4169.76 4257.33,4040.99 v2(4357.32,4040.99)
AA15: U1.194 U5.30 | length 1012.4
  Top Layer w9.92: v2(3408.55,4179.76) U5.30@3440,4179.76 ; v2(3877.02,4121.3) 3947.02,4051.3 4107.02,4051.3 4147.02,4011.3 4197.02,4011.3 4207.02,4021.3 U1.194@4307.32,4021.3
  Bottom Layer w9.92: v2(3408.55,4179.76) 3477.02,4111.3 3867.02,4111.3 v2(3877.02,4121.3)
AA16: U1.195 U5.2 | length 901
  Top Layer w9.92: U5.2@3640,4179.76 3640,4149.26 3687.64,4101.62 3767.64,4101.62 v2(3807.64,4141.62) ; U1.195@4307.32,4001.62 v2(4357.64,4001.62)
  Bottom Layer w9.92: v2(3807.64,4141.62) 3817.64,4151.62 4117.64,4151.62 4267.64,4001.62 v2(4357.64,4001.62)
AA17: U1.196 U5.31 | length 1025.6
  Top Layer w9.92: U5.31@3490,4179.76 3497.83,4171.93 3497.83,4124.85 3760,3862.68 4117.77,3862.68 4237.02,3981.93 U1.196@4307.32,3981.93
AA20: R8.1 U1.199 | length 267
  Top Layer w9.92: v2(4171.71,4058.19) R8.1@4171.71,4110.11 ; v2(4247.01,3942.88) 4267.01,3922.88 U1.199@4307.32,3922.88
  Bottom Layer w9.92: v2(4171.71,4058.19) 4247.01,3982.88 v2(4247.01,3942.88)
AA21: U1.200 U5.25 | length 1441.6
  Top Layer w9.92: U5.25@3372.09,4447.68 3342.09,4447.68 3312.52,4418.11 3312.52,4227.68 3427.02,4113.19 3479.49,4113.19 3750,3842.68 4146.51,3842.68 4207.02,3903.19 U1.200@4307.32,3903.19
AA22: ?.B16 U1.201 | length 1066.6
  Top Layer w9.92: ?.B16@3900.2,3185.04 3900.2,3297.88 4080.2,3477.88 v2(4080.2,3494.96) ; v2(4196.94,3809.85) 4196.94,3854.61 4225.83,3883.51 U1.201@4307.32,3883.51
  Top Layer w10: ?.B16@3900.2,3080.31 ?.B16@3900.2,3185.04
  Bottom Layer w9.92: v2(4080.2,3494.96) 4085.2,3494.96 4250.2,3659.96 4250.2,3756.59 v2(4196.94,3809.85)
AA23: R9.1 U1.28 | length 208.4
  Top Layer w9.92: U1.28@4919.53,3665 4919.53,3475.64 R9.1@4932.97,3462.21
AA24: ?.B40 U1.29 | length 651.4
  Top Layer w9.92: U1.29@4939.21,3665 4940.2,3664.01 4940.2,3519.96 4970.2,3489.96 4970.2,3409.96 5100.2,3279.96 ?.B40@5100.2,3185.04
  Top Layer w10: ?.B40@5100.2,3080.31 ?.B40@5100.2,3185.04
AA25: ?.B42 U1.30 | length 684.6
  Top Layer w9.92: U1.30@4958.9,3665 4958.9,3581.25 5200.2,3339.96 ?.B42@5200.2,3185.04
  Top Layer w10: ?.B42@5200.2,3080.31 ?.B42@5200.2,3185.04
ADS: ?.A34 U1.22 | length 688.3
  Top Layer w9.92: U1.22@4801.42,3665 4801.42,3711.27 v2(4805.15,3715)
  Bottom Layer w9.92: ?.A34@4800.2,3185.04 4800.2,3710.04 v2(4805.15,3715)
  Bottom Layer w10: ?.A34@4800.2,3080.31 ?.A34@4800.2,3185.04
BE0: ?.A52 U1.43 | length 908.6
  Top Layer w9.92: U1.43@5214.8,3665 5214.8,3625.36 5310.2,3529.96 5498.7,3529.96 5715.2,3313.47 v2(5715.2,3309.96)
  Bottom Layer w9.92: ?.A52@5700.19,3185.04 5700.2,3294.96 v2(5715.2,3309.96)
  Bottom Layer w10: ?.A52@5700.19,3080.31 ?.A52@5700.19,3185.04
BE1: ?.B44 U1.32 | length 709.7
  Top Layer w9.92: U1.32@4998.27,3665 5000.2,3663.08 5000.2,3579.96 5300.2,3279.96 ?.B44@5300.2,3185.04
  Top Layer w10: ?.B44@5300.2,3080.31 ?.B44@5300.2,3185.04
BE2: ?.B33 U1.21 | length 597.7
  Top Layer w9.92: ?.B33@4750.2,3185.04 4750.2,3279.96 4780.2,3309.96 4780.2,3663.47 U1.21@4781.73,3665
  Top Layer w10: ?.B33@4750.2,3080.31 ?.B33@4750.2,3185.04
BE3: ?.B26 U1.10 | length 653
  Top Layer w9.92: ?.B26@4400.2,3185.04 4400.2,3409.96 4565.2,3574.96 U1.10@4565.2,3665
  Top Layer w10: ?.B26@4400.2,3080.31 ?.B26@4400.2,3185.04
CASAH: R3.2 U1.159 | length 1082.2
  Top Layer w9.92: R3.2@3640.63,5397.21 3647.02,5390.82 v2(3647.02,5330.28) ; v2(3817.02,5000.28) 3957.4,5000.28 4198.56,4759.12 4201.54,4759.12 4207.95,4752.7 4207.95,4749.73 4247.4,4710.28 U1.159@4307.32,4710.28
  Bottom Layer w9.92: v2(3647.02,5330.28) 3817.02,5160.28 v2(3817.02,5000.28)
